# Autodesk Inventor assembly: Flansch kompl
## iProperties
Created: 2006-11
Part Number: Flansch kompl
Cost Center: 0,135 kg
Document SubType Name: Assembly
Designer: Schmidt
Authority: 17197 mm^3
Mass: 134.827 g
Surface Area: 81.7705 cm^2
Volume: 17.1973 cm^3
Density: 7.84 g/cm^3
SaveDate: 2006-11-07
SaveTime: 20:04
TotalMass: 0,135 kg
TotalVolume: 17197 mm^3
Author: Schmidt
